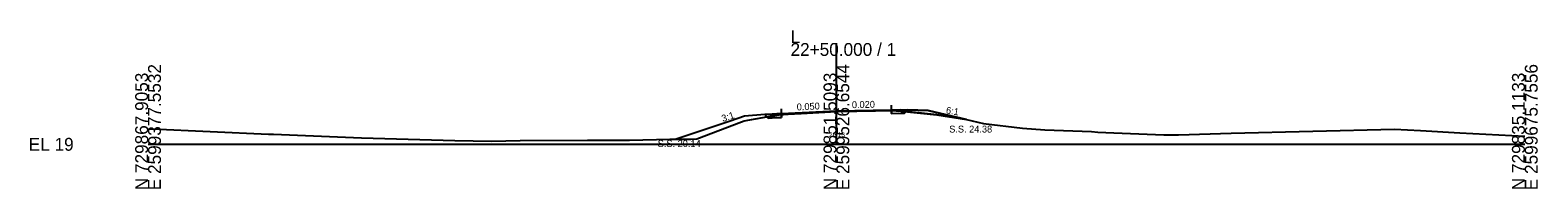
# Model space of a CAD drawing. Extents: x -26 to 3303, y -10 to 9555.
# Drawn here: x 1974.3 to 2302.8, y 4990.3 to 5024.9 of the extents above; entities that cross this region are included whole.
import ezdxf

# ---------------------------------------------------------------- set-up
doc = ezdxf.new("R2010")
doc.units = 0
for name, color, linetype in [('Exist Cross Section Cell', 7, 'Continuous'), ('Exist XS Center Line Elevation Label', 7, 'Continuous'), ('Exist XS Ground Line', 7, 'Continuous'), ('Prop XS Ditch Slope Text', 7, 'Continuous'), ('Prop XS Dump Level', 7, 'Continuous'), ('Prop XS Earthwork Shape', 7, 'Continuous'), ('Prop XS EOT Tick Mark', 7, 'Continuous'), ('Prop XS Finish Grade', 7, 'Continuous'), ('Prop XS Finish Grade Earthwork', 7, 'Continuous'), ('Prop XS Finish Grade Paved Shoulder', 7, 'Continuous'), ('Prop XS Finish Grade Pavement', 7, 'Continuous'), ('Prop XS Pvmt Edge Slope', 7, 'Continuous'), ('Prop XS SE Text', 7, 'Continuous'), ('Prop XS Side Slope Text', 7, 'Continuous'), ('Prop XS SS Elevation Text', 7, 'Continuous'), ('Prop XS Subgrade Earthwork', 7, 'Continuous')]:
    doc.layers.add(name, color=color, linetype=linetype)

msp = doc.modelspace()

# ---------------------------------------------------------------- linework, layer by layer
at = {"layer": 'Exist Cross Section Cell'}
for p, q in [((2150, 5000), (2150, 5022.06)), ((2000, 5000), (2150, 5000)), ((2150, 5000), (2300, 5000))]:
    msp.add_line(p, q, dxfattribs=at)
at = {"layer": 'Exist XS Ground Line'}
msp.add_lwpolyline([(2000, 5003.33), (2000.81, 5003.34), (2026.24, 5002.24), (2026.64, 5002.22), (2027.3, 5002.19), (2046.52, 5001.4), (2066.86, 5000.85), (2074.82, 5000.71), (2081.1, 5000.82), (2095.76, 5000.93), (2104.92, 5000.94), (2113.66, 5001.14), (2118.29, 5001.13), (2119.61, 5001.16), (2129.31, 5004.92), (2129.92, 5005.15), (2135.56, 5006.12), (2138.01, 5006.5), (2142.3, 5006.72), (2150, 5007.13), (2150.44, 5007.16), (2162.5, 5007.35), (2162.91, 5007.35), (2163.29, 5007.31), (2171.91, 5006.44), (2178.32, 5005.38), (2182.08, 5004.54), (2190.57, 5003.51), (2195.4, 5003.15), (2205.55, 5002.76), (2206.98, 5002.63), (2210.42, 5002.47), (2221.32, 5002.05), (2224.54, 5002.06), (2236.03, 5002.42), (2271.58, 5003.3), (2277.25, 5003.04), (2285.85, 5002.51), (2300, 5001.79)], dxfattribs=at)
at = {"layer": 'Prop XS Dump Level'}
for p, q in [((2138, 5006.7), (2150, 5007.3)), ((2150, 5007.3), (2162, 5007.54))]:
    msp.add_line(p, q, dxfattribs=at)
at = {"layer": 'Prop XS Earthwork Shape'}
for points in [[(2164.82, 5006.77), (2165.17, 5007.12), (2163.29, 5007.31), (2162.91, 5007.35), (2162.5, 5007.35), (2162, 5007.34), (2162, 5006.71), (2164, 5006.75)], [(2164, 5006.75), (2164.82, 5006.77), (2165.17, 5007.12), (2163.29, 5007.31), (2162.91, 5007.35), (2162.5, 5007.35), (2162, 5007.34), (2162, 5006.71)], [(2165.17, 5007.12), (2171.91, 5006.44), (2178.32, 5005.38), (2174, 5006.4), (2170, 5007.34), (2165.57, 5007.52)], [(2165.57, 5007.52), (2170, 5007.34), (2174, 5006.4), (2178.32, 5005.38), (2171.91, 5006.44), (2165.17, 5007.12)], [(2126.81, 5005.06), (2115.05, 5001.14), (2118.29, 5001.13), (2119.61, 5001.16), (2129.31, 5004.92), (2129.92, 5005.15), (2134.85, 5006), (2134.38, 5006.47), (2130, 5006.12)], [(2134.85, 5006), (2134.38, 5006.47), (2130, 5006.12), (2126.81, 5005.06), (2115.05, 5001.14), (2118.29, 5001.13), (2119.61, 5001.16), (2129.31, 5004.92), (2129.92, 5005.15)], [(2138, 5005.87), (2136, 5005.77), (2135.12, 5005.73), (2134.85, 5006), (2135.56, 5006.12), (2138.01, 5006.5)], [(2138, 5005.87), (2138.01, 5006.5), (2135.56, 5006.12), (2134.85, 5006), (2135.12, 5005.73), (2136, 5005.77)]]:
    msp.add_lwpolyline(points, close=True, dxfattribs=at)
at = {"layer": 'Prop XS EOT Tick Mark'}
for p, q in [((2138, 5006.7), (2138, 5007.7)), ((2162, 5007.54), (2162, 5008.54))]:
    msp.add_line(p, q, dxfattribs=at)
at = {"layer": 'Prop XS Finish Grade'}
for p, q in [((2164, 5007.58), (2165.57, 5007.52)), ((2136, 5006.6), (2134.38, 5006.47))]:
    msp.add_line(p, q, dxfattribs=at)
at = {"layer": 'Prop XS Finish Grade Earthwork'}
for p, q in [((2165.57, 5007.52), (2170, 5007.34)), ((2170, 5007.34), (2174, 5006.4)), ((2126.81, 5005.06), (2115.05, 5001.14)), ((2130, 5006.12), (2126.81, 5005.06)), ((2134.38, 5006.47), (2130, 5006.12)), ((2174, 5006.4), (2178.32, 5005.38))]:
    msp.add_line(p, q, dxfattribs=at)
at = {"layer": 'Prop XS Finish Grade Paved Shoulder'}
for p, q in [((2162, 5007.54), (2164, 5007.58)), ((2138, 5006.7), (2136, 5006.6))]:
    msp.add_line(p, q, dxfattribs=at)
at = {"layer": 'Prop XS Finish Grade Pavement'}
for p, q in [((2138, 5006.7), (2150, 5007.3)), ((2150, 5007.3), (2162, 5007.54))]:
    msp.add_line(p, q, dxfattribs=at)
at = {"layer": 'Prop XS Pvmt Edge Slope'}
for p, q in [((2164, 5007.58), (2164.82, 5006.77)), ((2164.82, 5006.77), (2165.57, 5007.52)), ((2135.12, 5005.73), (2134.38, 5006.47)), ((2136, 5006.6), (2135.12, 5005.73))]:
    msp.add_line(p, q, dxfattribs=at)
at = {"layer": 'Prop XS Subgrade Earthwork'}
for p, q in [((2162, 5006.71), (2162, 5007.34)), ((2164.82, 5006.77), (2165.57, 5007.52)), ((2135.12, 5005.73), (2134.38, 5006.47)), ((2136, 5005.77), (2135.12, 5005.73)), ((2138, 5005.87), (2136, 5005.77)), ((2138.01, 5005.87), (2138, 5005.87)), ((2138.01, 5005.87), (2138.01, 5006.5)), ((2162, 5006.71), (2164, 5006.75)), ((2164, 5006.75), (2164.82, 5006.77))]:
    msp.add_line(p, q, dxfattribs=at)

# ---------------------------------------------------------------- texts
at = {"layer": 'Exist Cross Section Cell'}
for s, p in [('L', (2140, 5022.06)), ('22+50.000 / 1', (2140, 5019.26)), ('EL 19', (1974, 4998.6))]:
    msp.add_text(s, height=2.8, dxfattribs=at).set_placement(p)
for s, p in [('E 2599377.5532', (2002.8, 4990)), ('E 2599526.6544', (2152.8, 4990)), ('E 2599675.7556', (2302.8, 4990)), ('N 729867.9053', (2000, 4990)), ('N 729851.5093', (2150, 4990)), ('N 729835.1133', (2300, 4990))]:
    msp.add_text(s, height=2.8, rotation=90, dxfattribs=at).set_placement(p)
at = {"layer": 'Exist XS Center Line Elevation Label'}
msp.add_text('26.13', height=1, dxfattribs=at).set_placement((2148.39, 5001.63))
at = {"layer": 'Prop XS Ditch Slope Text'}
msp.add_text('6:1', height=1.5, rotation=350.5377, dxfattribs=at).set_placement((2173.79, 5006.74))
at = {"layer": 'Prop XS Dump Level'}
for s, height, p in [('Eop', 0.3, (2162.91, 5007.05)), ('Case1', 0.04, (2170, 5007.3)), ('Case1', 0.04, (2130, 5006.08)), ('Eop', 0.3, (2138.01, 5006.2))]:
    msp.add_text(s, height=height, dxfattribs=at).set_placement(p)
at = {"layer": 'Prop XS SE Text'}
for s, rotation, p in [('0.050', 2.8624, (2141.38, 5007.37)), ('0.020', 1.1458, (2153.38, 5007.87))]:
    msp.add_text(s, height=1.5, rotation=rotation, dxfattribs=at).set_placement(p)
at = {"layer": 'Prop XS Side Slope Text'}
msp.add_text('3:1', height=1.5, rotation=18.4349, dxfattribs=at).set_placement((2125.26, 5004.85))
at = {"layer": 'Prop XS SS Elevation Text'}
for s, p in [('S.S. 24.38', (2174.57, 5002.57)), ('S.S. 20.14', (2111.05, 4999.41))]:
    msp.add_text(s, height=1.5, dxfattribs=at).set_placement(p)

doc.saveas('drawing.dxf')
